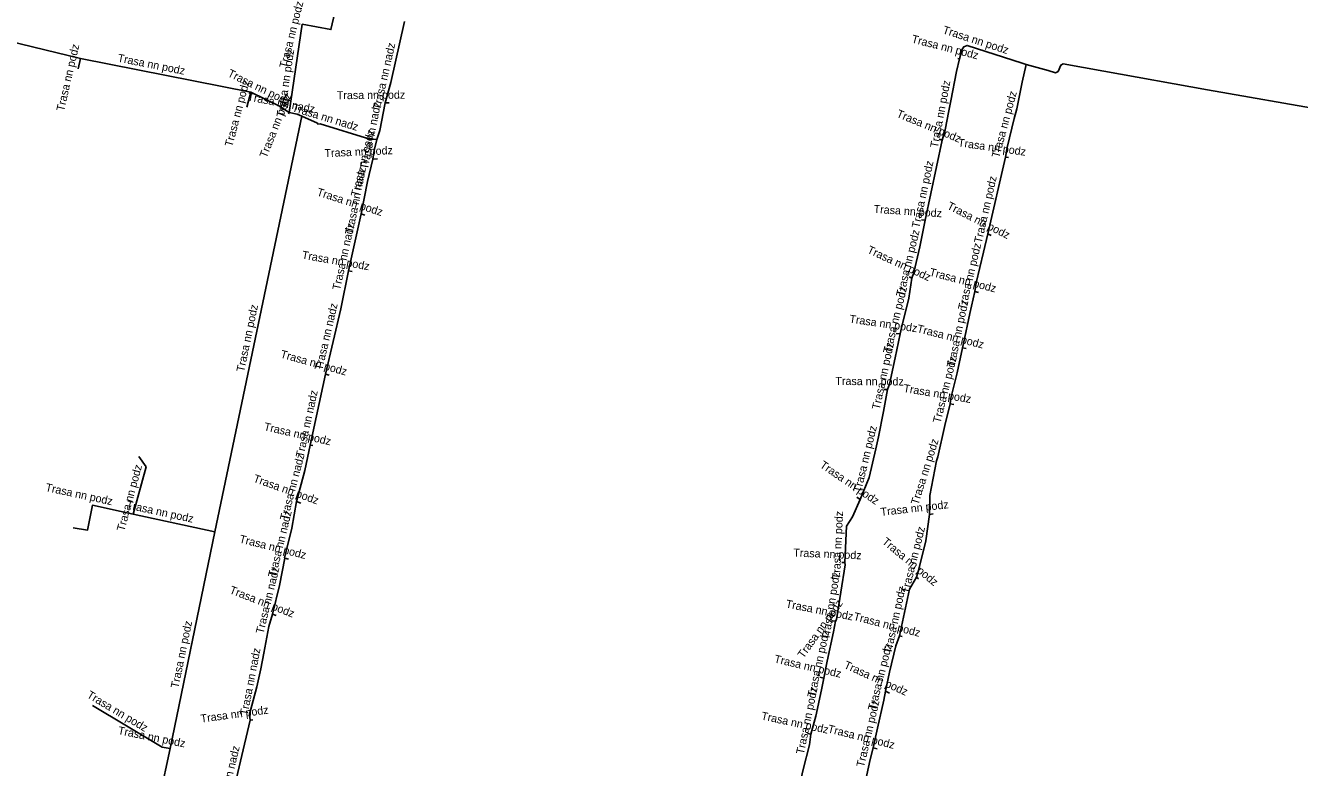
# Model space of a CAD drawing. Extents: x -737281 to -735046, y -1033441 to -1031241.
# Drawn here: x -735728.3 to -735569.1, y -1032050.4 to -1031957.7 of the extents above; entities that cross this region are included whole.
import ezdxf

# ---------------------------------------------------------------- set-up
doc = ezdxf.new("R2010")
doc.units = 0
doc.layers.add('Level 11', color=7, linetype='Continuous')
doc.layers.add('Level 20', color=7, linetype='Continuous')

msp = doc.modelspace()

# ---------------------------------------------------------------- linework, layer by layer
at = {"layer": 'Level 11'}
for p, q in [((-735721.4, -1031961.8), (-735769.1, -1031950.2)), ((-735693.7, -1031957.5), (-735695.33, -1031968.55)), ((-735721.4, -1031961.8), (-735721.7, -1031963.1)), ((-735700.1, -1031966), (-735721.4, -1031961.8)), ((-735611.78, -1031961.81), (-735611.58, -1031961.86)), ((-735700.1, -1031966), (-735700.6, -1031967.9)), ((-735683.34, -1031967.34), (-735682.83, -1031967.34)), ((-735704.6, -1032020.9), (-735693.75, -1031969.01)), ((-735695.4, -1031968.72), (-735695.33, -1031968.55)), ((-735613.74, -1031972.01), (-735615.87, -1031982)), ((-735614.12, -1031971.86), (-735613.74, -1031972.01)), ((-735605.85, -1031974.12), (-735608.03, -1031983.72)), ((-735605.85, -1031974.12), (-735605.48, -1031974.17)), ((-735684.87, -1031974.36), (-735684.31, -1031974.34)), ((-735687.91, -1031988.33), (-735686.35, -1031981.21)), ((-735686.35, -1031981.21), (-735685.88, -1031981.36)), ((-735615.87, -1031982), (-735616.33, -1031981.97)), ((-735608.03, -1031983.72), (-735607.65, -1031983.91)), ((-735687.91, -1031988.33), (-735687.45, -1031988.41)), ((-735617.54, -1031989.22), (-735617.89, -1031989.06)), ((-735609.68, -1031990.9), (-735609.21, -1031991.02)), ((-735619, -1031996.21), (-735619.48, -1031996.14)), ((-735611.22, -1031997.92), (-735610.76, -1031998.04)), ((-735692.68, -1032010.08), (-735690.78, -1032001.24)), ((-735690.78, -1032001.24), (-735690.34, -1032001.36)), ((-735620.6, -1032003.13), (-735621.04, -1032003.13)), ((-735612.75, -1032004.92), (-735612.3, -1032005)), ((-735692.68, -1032010.08), (-735692.37, -1032010.15)), ((-735694.39, -1032017.14), (-735693.87, -1032017.32)), ((-735623.99, -1032016.88), (-735624.41, -1032016.6)), ((-735704.6, -1032020.9), (-735714.8, -1032018.7)), ((-735615.32, -1032018.74), (-735614.86, -1032018.69)), ((-735710.2, -1032048), (-735704.6, -1032020.9)), ((-735695.87, -1032024.21), (-735695.42, -1032024.32)), ((-735625.92, -1032024.77), (-735626.3, -1032024.75)), ((-735616.95, -1032026.59), (-735616.69, -1032026.81)), ((-735697.42, -1032031.21), (-735696.95, -1032031.39)), ((-735627.09, -1032032.09), (-735627.45, -1032032.02)), ((-735626.94, -1032031.87), (-735627.09, -1032032.09)), ((-735619.1, -1032033.92), (-735618.76, -1032034)), ((-735628.55, -1032039.18), (-735629.02, -1032039.07)), ((-735620.83, -1032040.82), (-735620.33, -1032041.05)), ((-735711.2, -1032047.8), (-735719.9, -1032042.6)), ((-735702.88, -1032055.73), (-735700.18, -1032044.43)), ((-735700.18, -1032044.43), (-735699.87, -1032044.39)), ((-735630.16, -1032046.2), (-735630.59, -1032046.11)), ((-735714.1, -1032066.2), (-735710.2, -1032048)), ((-735710.2, -1032048), (-735711.2, -1032047.8)), ((-735622.39, -1032047.91), (-735621.89, -1032048.04))]:
    msp.add_line(p, q, dxfattribs=at)
for points in [[(-735679.98, -1031915.26), (-735690.1, -1031958.2), (-735693.7, -1031957.5)], [(-735680.91, -1031957.18), (-735682.63, -1031964.82), (-735683.34, -1031967.34)], [(-735611.58, -1031961.86), (-735611.29, -1031960.73), (-735611.05, -1031960.34), (-735610.62, -1031960.18), (-735603.78, -1031962.4), (-735603.27, -1031962.54)], [(-735613.74, -1031972.01), (-735613.36, -1031970.72), (-735612.92, -1031968.33), (-735612.67, -1031967.09), (-735611.98, -1031963.41), (-735611.58, -1031961.86)], [(-735603.27, -1031962.54), (-735603.74, -1031964.74), (-735604.44, -1031968.09), (-735604.76, -1031969.28), (-735605.64, -1031972.91), (-735605.85, -1031974.12)], [(-735603.27, -1031962.54), (-735600.51, -1031963.32), (-735599.58, -1031963.59), (-735599.27, -1031963.43), (-735598.92, -1031962.62), (-735598.65, -1031962.46), (-735593.57, -1031963.38), (-735580.59, -1031965.7), (-735565.82, -1031968.29), (-735549.04, -1031971.05), (-735542.52, -1031971.23), (-735537.72, -1031971.63), (-735537.42, -1031971.88), (-735537.27, -1031973.51), (-735535.58, -1031975.41), (-735535.86, -1031976.51), (-735536.42, -1031979.23), (-735536.62, -1031980.22), (-735537.15, -1031983.44), (-735537.56, -1031985.01), (-735537.94, -1031986.38)], [(-735695.33, -1031968.55), (-735696.54, -1031967.74), (-735700.1, -1031966)], [(-735683.34, -1031967.34), (-735684.01, -1031970.78), (-735684.39, -1031971.94), (-735684.39, -1031971.94)], [(-735693.75, -1031969.01), (-735694.32, -1031968.74), (-735695.33, -1031968.55)], [(-735693.75, -1031969.01), (-735691.8, -1031969.9), (-735691.73, -1031970), (-735691.46, -1031969.98), (-735685.24, -1031971.86), (-735684.41, -1031971.93)], [(-735684.39, -1031971.94), (-735684.72, -1031973.3), (-735684.87, -1031974.36)], [(-735686.35, -1031981.21), (-735685.55, -1031977.17), (-735684.87, -1031974.36)], [(-735617.54, -1031989.22), (-735617.31, -1031988.55), (-735616.53, -1031985.31), (-735615.87, -1031982)], [(-735608.03, -1031983.72), (-735608.59, -1031986.01), (-735609.5, -1031989.83), (-735609.68, -1031990.9)], [(-735690.78, -1032001.24), (-735688.87, -1031993.05), (-735687.91, -1031988.33)], [(-735619, -1031996.21), (-735618.85, -1031995.43), (-735617.93, -1031991.72), (-735617.54, -1031989.22)], [(-735611.22, -1031997.92), (-735611.07, -1031997.39), (-735610.28, -1031993.66), (-735609.68, -1031990.9)], [(-735620.6, -1032003.13), (-735620.35, -1032002.46), (-735619.64, -1031999.19), (-735619, -1031996.21)], [(-735612.75, -1032004.92), (-735612.66, -1032004.21), (-735611.88, -1032001.06), (-735611.22, -1031997.92)], [(-735620.6, -1032003.13), (-735621.09, -1032005.91), (-735621.69, -1032009.07), (-735622.05, -1032010.56), (-735622.89, -1032014.13), (-735623.99, -1032016.88)], [(-735612.75, -1032004.92), (-735613.44, -1032007.66), (-735614.3, -1032011.56), (-735614.45, -1032012.04), (-735615.31, -1032016.39), (-735615.32, -1032018.74)], [(-735694.39, -1032017.14), (-735693.38, -1032013.24), (-735692.68, -1032010.08)], [(-735714.8, -1032018.7), (-735713.2, -1032012.8), (-735714.1, -1032011.5)], [(-735694.39, -1032017.14), (-735694.98, -1032020.46), (-735695.89, -1032024.18), (-735695.87, -1032024.21)], [(-735623.99, -1032016.88), (-735624.97, -1032019.06), (-735625.71, -1032020.23), (-735625.92, -1032024.77)], [(-735714.8, -1032018.7), (-735719.9, -1032017.6), (-735720.5, -1032020.7), (-735722.3, -1032020.4)], [(-735615.32, -1032018.74), (-735615.78, -1032022.04), (-735616.7, -1032025.74), (-735616.95, -1032026.59)], [(-735697.42, -1032031.21), (-735696.55, -1032027.61), (-735695.87, -1032024.21)], [(-735626.94, -1032031.87), (-735625.85, -1032025.05), (-735625.92, -1032024.77)], [(-735616.95, -1032026.59), (-735617.83, -1032028.08), (-735619.1, -1032033.92)], [(-735700.18, -1032044.43), (-735700.27, -1032043.71), (-735699.35, -1032040.29), (-735698.87, -1032038.02), (-735698.49, -1032036.06), (-735697.85, -1032032.74), (-735697.42, -1032031.21)], [(-735627.09, -1032032.09), (-735627.33, -1032033.41), (-735628.12, -1032037.06), (-735628.55, -1032039.18)], [(-735619.1, -1032033.92), (-735619.52, -1032035.14), (-735620.35, -1032038.43), (-735620.83, -1032040.82)], [(-735628.55, -1032039.18), (-735628.84, -1032040.65), (-735629.53, -1032043.96), (-735630.16, -1032046.2)], [(-735620.83, -1032040.82), (-735621.02, -1032041.93), (-735621.85, -1032045.45), (-735622.39, -1032047.91)], [(-735630.16, -1032046.2), (-735630.31, -1032047.53), (-735631.13, -1032050.62), (-735633.21, -1032059.74)], [(-735622.39, -1032047.91), (-735622.73, -1032049.34), (-735623.58, -1032053.2), (-735624.55, -1032057.29), (-735625.37, -1032061.46)]]:
    msp.add_lwpolyline(points, dxfattribs=at)

# ---------------------------------------------------------------- texts
at = {"layer": 'Level 20'}
for s, rotation, p in [('Trasa nn podz', 75.9638, (-735695.61, -1031963.08)), ('Trasa nn podz', 342.0788, (-735613.77, -1031958.64)), ('Trasa nn nadz', 77.3093, (-735683.93, -1031968.3)), ('Trasa nn podz', 345.556, (-735617.64, -1031959.79)), ('Trasa nn podz', 77.0054, (-735723.45, -1031968.46)), ('Trasa nn podz', 348.8453, (-735716.82, -1031962.19)), ('Trasa nn podz', 81.6007, (-735695.93, -1031969.17)), ('Trasa nn podz', 333.9852, (-735703.1, -1031963.98)), ('Trasa nn podz', 75.2564, (-735702.43, -1031972.9)), ('Trasa nn podz', 79.3869, (-735614.29, -1031973.03)), ('Trasa nn nadz', 349.2986, (-735700.6, -1031967.04)), ('Trasa nn podz', 68.4222, (-735698.14, -1031974.3)), ('Trasa nn podz', 0.4511, (-735689.37, -1031966.89)), ('Trasa nn podz', 74.9729, (-735606.63, -1031974.28)), ('Trasa nn nadz', 343.0971, (-735695.04, -1031968.37)), ('Trasa nn nadz', 78.8956, (-735685.49, -1031975.73)), ('Trasa nn podz', 337.4347, (-735619.54, -1031969.06)), ('Trasa nn nadz', 76.2443, (-735686.67, -1031979.13)), ('Trasa nn podz', 352.0886, (-735611.82, -1031972.78)), ('Trasa nn podz', 2.5607, (-735690.89, -1031974.13)), ('Trasa nn nadz', 78.7555, (-735687.38, -1031983.84)), ('Trasa nn podz', 77.9836, (-735616.6, -1031983.05)), ('Trasa nn podz', 77.2022, (-735608.82, -1031984.94)), ('Trasa nn podz', 342.2642, (-735691.95, -1031978.89)), ('Trasa nn podz', 356.2524, (-735622.34, -1031981.08)), ('Trasa nn podz', 333.1917, (-735613.23, -1031980.53)), ('Trasa nn nadz', 77.6417, (-735688.97, -1031990.8)), ('Trasa nn podz', 76.3765, (-735618.57, -1031991.63)), ('Trasa nn podz', 335.1428, (-735623.21, -1031986.04)), ('Trasa nn podz', 76.6885, (-735610.83, -1031993.3)), ('Trasa nn podz', 350.092, (-735693.79, -1031986.79)), ('Trasa nn podz', 345.6773, (-735615.42, -1031988.92)), ('Trasa nn podz', 75.9892, (-735620.19, -1031998.71)), ('Trasa nn podz', 78.1939, (-735700.95, -1032001.01)), ('Trasa nn nadz', 76.8936, (-735691.19, -1032000.81)), ('Trasa nn podz', 78.0657, (-735612.23, -1032000.46)), ('Trasa nn podz', 351.8533, (-735625.39, -1031994.79)), ('Trasa nn podz', 346.081, (-735616.97, -1031995.98)), ('Trasa nn podz', 77.7483, (-735621.57, -1032005.72)), ('Trasa nn podz', 344.633, (-735696.49, -1031999.15)), ('Trasa nn podz', 76.0537, (-735613.97, -1032007.41)), ('Trasa nn podz', 359.4756, (-735627.1, -1032002.57)), ('Trasa nn podz', 350.6633, (-735618.65, -1032003.45)), ('Trasa nn nadz', 77.8618, (-735693.54, -1032011.7)), ('Trasa nn podz', 347.1302, (-735698.54, -1032008.22)), ('Trasa nn podz', 76.3336, (-735623.91, -1032016.09)), ('Trasa nn podz', 72.5373, (-735616.74, -1032017.63)), ('Trasa nn nadz', 75.4569, (-735695.54, -1032019.58)), ('Trasa nn podz', 325.8735, (-735629.12, -1032012.8)), ('Trasa nn podz', 74.8271, (-735715.92, -1032020.92)), ('Trasa nn podz', 340.416, (-735699.89, -1032014.65)), ('Trasa nn podz', 347.8285, (-735725.83, -1032015.81)), ('Trasa nn podz', 347.8285, (-735715.74, -1032017.99)), ('Trasa nn podz', 6.5584, (-735621.39, -1032018.94)), ('Trasa nn nadz', 76.2644, (-735697.02, -1032026.69)), ('Trasa nn podz', 87.4513, (-735626.51, -1032026.87)), ('Trasa nn podz', 75.9528, (-735617.95, -1032028.69)), ('Trasa nn podz', 345.8737, (-735701.62, -1032022.24)), ('Trasa nn podz', 320.2833, (-735621.34, -1032022.3)), ('Trasa nn podz', 357.6078, (-735632.37, -1032024)), ('Trasa nn nadz', 76.3616, (-735698.54, -1032033.72)), ('Trasa nn podz', 80.9042, (-735627.86, -1032034.45)), ('Trasa nn podz', 338.7845, (-735702.86, -1032028.56)), ('Trasa nn podz', 77.7377, (-735620.11, -1032036.19)), ('Trasa nn podz', 348.9365, (-735633.35, -1032030.36)), ('Trasa nn podz', 54.437, (-735631.08, -1032036.8)), ('Trasa nn podz', 345.6432, (-735624.9, -1032031.92)), ('Trasa nn podz', 78.3246, (-735709.16, -1032040.51)), ('Trasa nn podz', 77.7463, (-735629.64, -1032041.67)), ('Trasa nn nadz', 79.0004, (-735700.52, -1032043.91)), ('Trasa nn podz', 347.0054, (-735634.8, -1032037.23)), ('Trasa nn podz', 75.8614, (-735622.09, -1032043.32)), ('Trasa nn podz', 335.7107, (-735626.11, -1032037.9)), ('Trasa nn podz', 329.1332, (-735720.69, -1032041.55)), ('Trasa nn podz', 78.2889, (-735631.04, -1032048.77)), ('Trasa nn podz', 7.6185, (-735706.32, -1032044.75)), ('Trasa nn podz', 76.8094, (-735623.52, -1032050.38)), ('Trasa nn podz', 347.9322, (-735636.42, -1032044.35)), ('Trasa nn podz', 348.6901, (-735716.77, -1032046.18)), ('Trasa nn podz', 345.9365, (-735628.11, -1032045.96)), ('Trasa nn nadz', 76.5858, (-735703.47, -1032056.08))]:
    msp.add_text(s, height=1, rotation=rotation, dxfattribs=at).set_placement(p)

doc.saveas('drawing.dxf')
